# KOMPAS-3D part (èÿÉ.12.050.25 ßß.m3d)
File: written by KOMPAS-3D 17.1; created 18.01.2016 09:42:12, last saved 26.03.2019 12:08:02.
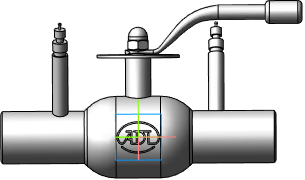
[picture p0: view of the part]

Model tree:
1. Операция без истории:5  (labels: Сталь 20  ГОСТ 1050-88)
